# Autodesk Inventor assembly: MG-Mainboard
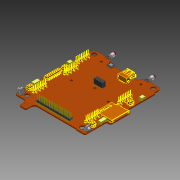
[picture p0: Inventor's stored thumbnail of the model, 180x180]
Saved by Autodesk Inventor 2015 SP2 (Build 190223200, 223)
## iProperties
Created: 2015-08
Part Number: MG-Mainboard
Document SubType Name: Assembly
Designer: rYan
Mass: 27.3208 g
Surface Area: 291.912 cm^2
Volume: 20.4266 cm^3
Density: 1.33751 g/cm^3
Author: rYan
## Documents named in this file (14)
- D:\TIGERs GIT\Hardware\mechanik\2016\Inventor\Elektronik\MG-Mainboard.iam
- D:\TIGERs GIT\Hardware\mechanik\2016\Inventor\Elektronik\Mainboard.ipt
- D:\TIGERs GIT\Hardware\mechanik\2016\Inventor\Kaufteile\TSM-120-01-T-DV-P\TSM-120-01-T-DV-P.iam
- D:\TIGERs GIT\Hardware\mechanik\2016\Inventor\Kaufteile\Micromatch F16.ipt
- D:\TIGERs GIT\Hardware\mechanik\2016\Inventor\Kaufteile\AMPMODU 8P.ipt
- D:\TIGERs GIT\Hardware\mechanik\2016\Inventor\Kaufteile\SDCard.ipt
- D:\TIGERs GIT\Hardware\mechanik\2016\Inventor\Kaufteile\KT11P4.ipt
- D:\TIGERs GIT\Hardware\mechanik\2016\Inventor\Kaufteile\Micromatch F4.ipt
- D:\TIGERs GIT\Hardware\mechanik\2016\Inventor\Kaufteile\Micro-USB.ipt
- D:\TIGERs GIT\Hardware\mechanik\2016\Inventor\Kaufteile\SSM-105-L-DV\SSM-105-L-DV.iam
- D:\TIGERs GIT\Hardware\mechanik\2016\Inventor\Kaufteile\USB-A.ipt
- D:\TIGERs GIT\Hardware\mechanik\2016\Inventor\Kaufteile\DF13A-3P-1.25H.ipt
- D:\TIGERs GIT\Hardware\mechanik\2016\Inventor\Kaufteile\DF13A-6P-1.25H.ipt
- D:\TIGERs GIT\Hardware\mechanik\2016\Inventor\Kaufteile\Duo-LED.ipt
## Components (24 placed, 13 different names)
1. Mainboard:1 — Fluchtend:1, Passend:2, Passend:3, Passend:4, Passend:5, Passend:6, Passend:7, Passend:8, Passend:9, Passend:11, Fluchtend:2, Passend:15, Passend:16, Fluchtend:5, Fluchtend:6, Fluchtend:8, Fluchtend:11, Fluchtend:12, Fluchtend:13, Fluchtend:14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
2. TSM-120-01-T-DV-P:1 [sub-assembly] — Passend:2, Fluchtend:18, Fluchtend:29
3. Micromatch F16:1 — Passend:11, Fluchtend:8, Fluchtend:19
4. AMPMODU 8P:1 — Passend:5, Fluchtend:12, Passend:19
5. AMPMODU 8P:2 — Passend:6, Fluchtend:11, Fluchtend:22, Passend:20
6. AMPMODU 8P:3 — Passend:7, Fluchtend:6, Fluchtend:22, Fluchtend:26
7. AMPMODU 8P:4 — Passend:8, Fluchtend:5, Passend:21
8. AMPMODU 8P:5 — Passend:9, Fluchtend:13, Fluchtend:28
9. SDCard:1 — Fluchtend:1, Fluchtend:2, Fluchtend:26
10. KT11P4:1 — Passend:4, Fluchtend:37, Fluchtend:38
11. KT11P4:2 — Passend:3, Fluchtend:36, Fluchtend:39
12. Micromatch F4:1 — Passend:15
13. Micro-USB 47346-0001:1 — Passend:16, Fluchtend:14, Passend:28
14. SSM-105-L-DV:1 [sub-assembly] — Passend:23, Fluchtend:35, Passend:27
15. USB-A:1 — Passend:24, Fluchtend:32, Passend:29
16. DF13A-3P-1.25H:1 — Passend:30, Fluchtend:40
17. DF13A-3P-1.25H:2 — Passend:33, Fluchtend:44
18. DF13A-6P-1.25H:1 — Passend:32, Fluchtend:42, Fluchtend:43
19. DF13A-6P-1.25H:2 — Passend:31, Fluchtend:41, Fluchtend:43
20. Micromatch F4:2 — Passend:35
21. Micromatch F4:3 — Passend:34
22. Micromatch F4:4 — Passend:36
23. Duo-LED:1 — Einfügen:1, Winkel:2
24. Duo-LED:2 — Einfügen:2, Winkel:1
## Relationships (56: Flush 26, Mate 26, Insert 2, Angle 2)
- Fluchtend:1 [Flush]: Mainboard:1 ↔ SDCard:1
- Passend:2 [Mate]: Mainboard:1 ↔ TSM-120-01-T-DV-P:1
- Passend:3 [Mate]: Mainboard:1 ↔ KT11P4:2
- Passend:4 [Mate]: Mainboard:1 ↔ KT11P4:1
- Passend:5 [Mate]: Mainboard:1 ↔ AMPMODU 8P:1
- Passend:6 [Mate]: Mainboard:1 ↔ AMPMODU 8P:2
- Passend:7 [Mate]: Mainboard:1 ↔ AMPMODU 8P:3
- Passend:8 [Mate]: Mainboard:1 ↔ AMPMODU 8P:4
- Passend:9 [Mate]: Mainboard:1 ↔ AMPMODU 8P:5
- Passend:11 [Mate]: Mainboard:1 ↔ Micromatch F16:1
- Fluchtend:2 [Flush]: Mainboard:1 ↔ SDCard:1
- Passend:15 [Mate]: Mainboard:1 ↔ Micromatch F4:1
- Passend:16 [Mate]: Mainboard:1 ↔ Micro-USB 47346-0001:1
- Fluchtend:5 [Flush]: Mainboard:1 ↔ AMPMODU 8P:4
- Fluchtend:6 [Flush]: Mainboard:1 ↔ AMPMODU 8P:3
- Fluchtend:8 [Flush]: Mainboard:1 ↔ Micromatch F16:1
- Fluchtend:11 [Flush]: Mainboard:1 ↔ AMPMODU 8P:2
- Fluchtend:12 [Flush]: Mainboard:1 ↔ AMPMODU 8P:1
- Fluchtend:13 [Flush]: Mainboard:1 ↔ AMPMODU 8P:5
- Fluchtend:14 [Flush]: Mainboard:1 ↔ Micro-USB 47346-0001:1
- Fluchtend:18 [Flush]: Mainboard:1 ↔ TSM-120-01-T-DV-P:1
- Fluchtend:19 [Flush]: Mainboard:1 ↔ Micromatch F16:1
- Fluchtend:22 [Flush]: AMPMODU 8P:2 ↔ AMPMODU 8P:3
- Fluchtend:26 [Flush]: AMPMODU 8P:3 ↔ SDCard:1
- Fluchtend:28 [Flush]: Mainboard:1 ↔ AMPMODU 8P:5
- Passend:19 [Mate]: Mainboard:1 ↔ AMPMODU 8P:1
- Passend:20 [Mate]: Mainboard:1 ↔ AMPMODU 8P:2
- Fluchtend:29 [Flush]: TSM-120-01-T-DV-P:1
- Passend:21 [Mate]: AMPMODU 8P:4
- Passend:23 [Mate]: Mainboard:1 ↔ SSM-105-L-DV:1
- Passend:24 [Mate]: Mainboard:1 ↔ USB-A:1
- Fluchtend:32 [Flush]: Mainboard:1 ↔ USB-A:1
- Fluchtend:35 [Flush]: SSM-105-L-DV:1
- Passend:27 [Mate]: SSM-105-L-DV:1
- Passend:28 [Mate]: Mainboard:1 ↔ Micro-USB 47346-0001:1
- Passend:29 [Mate]: Mainboard:1 ↔ USB-A:1
- Fluchtend:36 [Flush]: Mainboard:1 ↔ KT11P4:2
- Fluchtend:37 [Flush]: Mainboard:1 ↔ KT11P4:1
- Fluchtend:38 [Flush]: Mainboard:1 ↔ KT11P4:1
- Fluchtend:39 [Flush]: Mainboard:1 ↔ KT11P4:2
- Passend:30 [Mate]: Mainboard:1 ↔ DF13A-3P-1.25H:1
- Fluchtend:40 [Flush]: Mainboard:1 ↔ DF13A-3P-1.25H:1
- Passend:31 [Mate]: Mainboard:1 ↔ DF13A-6P-1.25H:2
- Fluchtend:41 [Flush]: Mainboard:1 ↔ DF13A-6P-1.25H:2
- Passend:32 [Mate]: Mainboard:1 ↔ DF13A-6P-1.25H:1
- Fluchtend:42 [Flush]: Mainboard:1 ↔ DF13A-6P-1.25H:1
- Fluchtend:43 [Flush]: DF13A-6P-1.25H:1 ↔ DF13A-6P-1.25H:2
- Passend:33 [Mate]: Mainboard:1 ↔ DF13A-3P-1.25H:2
- Fluchtend:44 [Flush]: Mainboard:1 ↔ DF13A-3P-1.25H:2
- Passend:34 [Mate]: Mainboard:1 ↔ Micromatch F4:3
- Passend:35 [Mate]: Mainboard:1 ↔ Micromatch F4:2
- Passend:36 [Mate]: Mainboard:1 ↔ Micromatch F4:4
- Einfügen:1 [Insert]: Mainboard:1 ↔ Duo-LED:1
- Einfügen:2 [Insert]: Mainboard:1 ↔ Duo-LED:2
- Winkel:1 [Angle]: Mainboard:1 ↔ Duo-LED:2
- Winkel:2 [Angle]: Mainboard:1 ↔ Duo-LED:1
